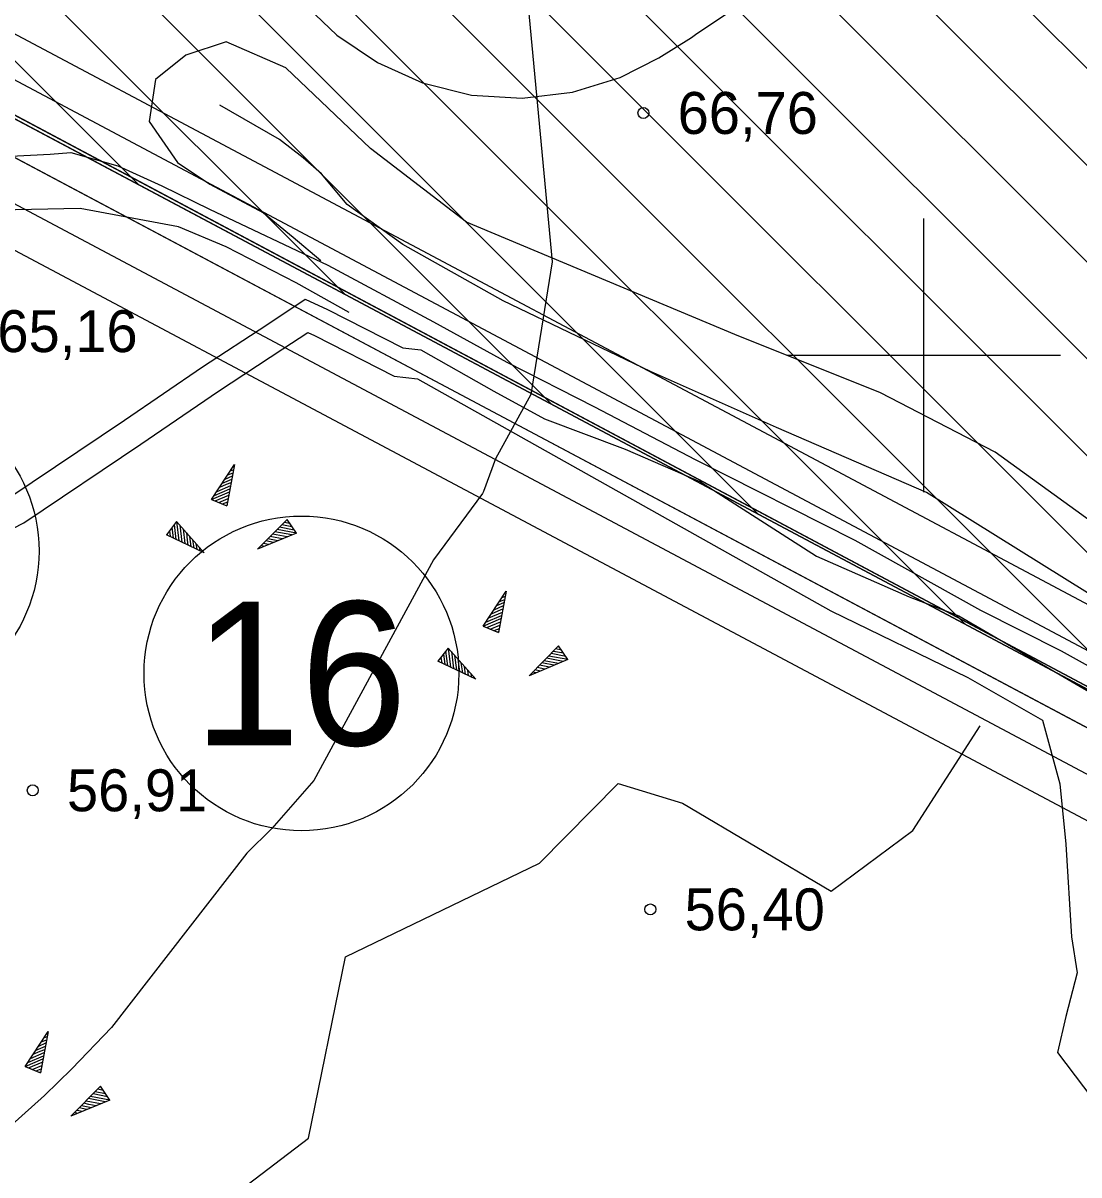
# Model space of a CAD drawing. Extents: x 532503 to 539665, y 6557663 to 6561526.
# Drawn here: x 534947.4 to 535009.1, y 6559752.1 to 6559819.4 of the extents above; entities that cross this region are included whole.
import ezdxf

# ---------------------------------------------------------------- set-up
doc = ezdxf.new("R2010")
doc.units = 0
for name, color, linetype in [('Default', 7, 'Continuous'), ('illumineerimisjooned', 7, 'Continuous'), ('Kaevandatud ala', 7, 'Continuous'), ('kataster', 7, 'Continuous'), ('KORGUS-EH2000', 7, 'Continuous'), ('Lamami horisontaal_EH2000', 7, 'Continuous'), ('ME_aktiivne', 7, 'Continuous'), ('PIIR', 7, 'Continuous'), ('PIIR_me', 7, 'Continuous'), ('Plokid', 7, 'Continuous'), ('RELJEEF', 7, 'Continuous'), ('TM_aktiivne', 7, 'Continuous'), ('VORK', 7, 'Continuous')]:
    doc.layers.add(name, color=color, linetype=linetype)

# ---------------------------------------------------------------- blocks, each defined once
blk = doc.blocks.new('POINT_DISPLAY')
at = {"layer": 'Default'}
blk.add_line((0, 0), (0, 0), dxfattribs=at)

msp = doc.modelspace()

# ---------------------------------------------------------------- linework, layer by layer
at = {"layer": 'illumineerimisjooned'}
for points in [[(534195.15, 6559981.187), (534198.982, 6559981.551), (535160.123, 6560071.768), (535418.528, 6559993.818), (535458.873, 6559929.252), (535494.628, 6559867.696), (535482.599, 6559826.001), (535251.738, 6559649.676), (535250.358, 6559648.526), (535180.445, 6559687.333), (534941.147, 6559814.594), (534876.935, 6559774.719), (534959.617, 6559531.323), (534733.77, 6559483.152), (534375.905, 6559461.866), (534195.514, 6559444.474)], [(535103.273, 6559501.74), (534971.344, 6559496.804), (534876.945, 6559774.719), (534941.147, 6559814.604), (535178.869, 6559688.171)], [(534960.711, 6559535.564), (534879.83, 6559773.686), (534941.24, 6559811.836), (535177.962, 6559685.935)]]:
    msp.add_lwpolyline(points, dxfattribs=at)
msp.add_lwpolyline([(534967.673, 6560049.69), (534974.155, 6559828.082), (535058.693, 6559883.051), (535223.499, 6560002.448), (535218.56, 6560049.918), (535415.933, 6559990.422), (535455.447, 6559927.188), (535490.312, 6559867.164), (535479.121, 6559828.379), (535249.574, 6559653.049), (535182.36, 6559690.845), (534940.993, 6559819.216), (534872.135, 6559776.441), (534954.369, 6559534.338), (534950.911, 6559533.67), (534733.22, 6559487.117), (534375.585, 6559465.864), (534199.951, 6559448.922), (533951.788, 6559660.129), (534200.214, 6559977.649), (534931.627, 6560046.309)], close=True, dxfattribs=at)
at = {"layer": 'Kaevandatud ala'}
for p, q in [((534955.885, 6559847.793), (535038.684, 6559764.994)), ((534952.616, 6559845.405), (535026.601, 6559771.42)), ((534948.592, 6559843.772), (535014.517, 6559777.847)), ((534942.035, 6559839.015), (534990.35, 6559790.7)), ((534947.823, 6559838.884), (535002.434, 6559784.273)), ((534940.755, 6559834.638), (534978.267, 6559797.127)), ((534935.513, 6559834.224), (534966.183, 6559803.553)), ((534932.015, 6559832.065), (534954.1, 6559809.98)), ((534977.01, 6559832.324), (535050.768, 6559758.567)), ((534984.096, 6559830.895), (535062.851, 6559752.14)), ((534996.108, 6559830.198), (535087.018, 6559739.287)), ((534991.44, 6559829.208), (535074.935, 6559745.714))]:
    msp.add_line(p, q, dxfattribs=at)
msp.add_lwpolyline([(534874.54, 6559775.58), (534941.07, 6559816.91), (535181.4, 6559689.09)], dxfattribs=at)
at = {"layer": 'kataster'}
for points in [[(533947.7, 6559658.95), (533949.2, 6559955.8), (534198.28, 6559979.48), (535159.89, 6560069.73), (535417.31, 6559992.13), (535457.22, 6559928.24), (535504.86, 6559846.09), (535250.3, 6559650.84), (535181.52, 6559689.04), (534941.15, 6559817.08), (534874.65, 6559775.26), (534957.01, 6559532.73), (534735.22, 6559485.45), (534375.71, 6559463.85), (534199.28, 6559446.9), (534122.84, 6559439.44), (534110.45, 6559447.36), (534092.53, 6559453.94), (534085.13, 6559454.75)], [(534957.01, 6559532.73), (534874.65, 6559775.26), (534941.15, 6559817.08), (535181.52, 6559689.04), (535104.64, 6559499.79), (534969.93, 6559494.75)]]:
    msp.add_lwpolyline(points, close=True, dxfattribs=at)
at = {"layer": 'KORGUS-EH2000'}
for centre in [(534983.62, 6559814.165), (534947.922, 6559774.569), (534984.024, 6559767.607)]:
    msp.add_circle(centre, 0.32, dxfattribs=at)
at = {"layer": 'Lamami horisontaal_EH2000'}
msp.add_lwpolyline([(534948.61, 6559868.336), (534959.559, 6559855.631), (534962.846, 6559852.329), (534963.478, 6559851.608), (534969.311, 6559840.662), (534970.343, 6559839.3), (534974.316, 6559830.834), (534976.179, 6559827.865), (534978.276, 6559805.462), (534977.047, 6559797.709), (534974.967, 6559793.942), (534974.262, 6559792.029), (534974.206, 6559791.92), (534971.342, 6559788.044), (534964.361, 6559775.147), (534961.905, 6559772.338), (534960.442, 6559770.885), (534952.529, 6559760.708), (534950.203, 6559758.284), (534948.61, 6559756.736), (534944.621, 6559753.17)], dxfattribs=at)
at = {"layer": 'ME_aktiivne'}
msp.add_lwpolyline([(534874.54, 6559775.58), (534941.07, 6559816.91), (535181.4, 6559689.09), (535131.71, 6559566.56), (534957, 6559532.81)], close=True, dxfattribs=at)
at = {"layer": 'PIIR'}
for centre in [(534939.089, 6559788.556), (534963.629, 6559781.403)]:
    msp.add_circle(centre, 9.2, dxfattribs=at)
at = {"layer": 'PIIR_me'}
msp.add_lwpolyline([(534441.63, 6560002.32), (534688.17, 6560025.46), (534931.44, 6560048.3), (534969.61, 6560051.877), (534976.05, 6559831.7), (535057.56, 6559884.7), (535221.39, 6560003.39), (535216.26, 6560052.7), (535417.23, 6559992.12), (535457.16, 6559928.22), (535492.47, 6559867.43), (535480.86, 6559827.19), (535250.12, 6559650.95), (535250.12, 6559650.95), (535181.4, 6559689.09), (534941.07, 6559816.91), (534874.54, 6559775.58), (534957, 6559532.81), (534951.31, 6559531.71), (534733.49, 6559485.13), (534485.11, 6559470.37)], dxfattribs=at)
at = {"layer": 'Plokid'}
for points in [[(535473.831, 6559827.358), (535249.729, 6559656.195), (535183.501, 6559692.956), (534940.9, 6559821.974), (534869.24, 6559777.474), (534950.465, 6559538.369)], [(534963.6, 6559820.725), (534965.689, 6559818.717), (534968.069, 6559817.12), (534970.705, 6559815.928), (534973.573, 6559815.215), (534976.526, 6559815.029), (534979.466, 6559815.379), (534982.252, 6559816.24), (534984.52, 6559817.392), (534986.425, 6559818.585), (534986.744, 6559818.81), (534989.344, 6559820.554)], [(534961.532, 6559540.611), (534882.716, 6559772.654), (534941.333, 6559809.068), (535174.925, 6559684.832)]]:
    msp.add_lwpolyline(points, dxfattribs=at)
at = {"layer": 'RELJEEF'}
for p, q in [((534958.377, 6559791.563), (534959.721, 6559793.611)), ((534959.721, 6559793.611), (534959.273, 6559791.195)), ((534959.641, 6559793.483), (534959.705, 6559793.515)), ((534959.017, 6559792.523), (534959.561, 6559792.763)), ((534959.177, 6559792.763), (534959.593, 6559792.955)), ((534959.321, 6559793.003), (534959.641, 6559793.131)), ((534959.481, 6559793.243), (534959.673, 6559793.323)), ((534958.377, 6559791.563), (534959.417, 6559792.011)), ((534958.537, 6559791.803), (534959.449, 6559792.187)), ((534958.697, 6559792.043), (534959.497, 6559792.379)), ((534958.857, 6559792.283), (534959.257, 6559792.459)), ((534959.257, 6559792.459), (534959.529, 6559792.571)), ((534958.377, 6559791.563), (534959.273, 6559791.195)), ((534958.585, 6559791.483), (534959.385, 6559791.819)), ((534958.793, 6559791.387), (534959.353, 6559791.627)), ((534959.017, 6559791.307), (534959.321, 6559791.435)), ((534959.225, 6559791.227), (534959.273, 6559791.243)), ((534956.324, 6559790.28), (534955.732, 6559789.512)), ((534956.18, 6559790.104), (534956.292, 6559789.24)), ((534956.324, 6559790.28), (534957.94, 6559788.456)), ((534956.324, 6559790.28), (534956.468, 6559789.16)), ((534956.516, 6559790.072), (534956.644, 6559789.08)), ((534961.058, 6559788.664), (534962.786, 6559790.408)), ((534963.074, 6559789.976), (534962.482, 6559790.088)), ((534962.946, 6559790.168), (534962.626, 6559790.232)), ((534962.818, 6559790.36), (534962.754, 6559790.36)), ((534963.33, 6559789.608), (534962.786, 6559790.408)), ((534957.94, 6559788.456), (534955.732, 6559789.512)), ((534955.764, 6559789.56), (534955.78, 6559789.496)), ((534955.908, 6559789.736), (534955.956, 6559789.416)), ((534956.052, 6559789.928), (534956.132, 6559789.336)), ((534956.708, 6559789.848), (534956.82, 6559789)), ((534956.9, 6559789.64), (534956.948, 6559789.192)), ((534957.076, 6559789.416), (534957.172, 6559788.824)), ((534963.33, 6559789.608), (534961.058, 6559788.664)), ((534962.098, 6559789.352), (534961.81, 6559789.416)), ((534962.786, 6559789.384), (534961.938, 6559789.544)), ((534963.058, 6559789.496), (534962.082, 6559789.688)), ((534962.53, 6559789.272), (534962.098, 6559789.352)), ((534963.33, 6559789.608), (534962.21, 6559789.816)), ((534963.202, 6559789.784), (534962.354, 6559789.96)), ((534956.948, 6559789.192), (534956.996, 6559788.904)), ((534957.268, 6559789.208), (534957.332, 6559788.744)), ((534957.46, 6559788.984), (534957.508, 6559788.664)), ((534957.652, 6559788.776), (534957.684, 6559788.568)), ((534961.186, 6559788.712), (534961.138, 6559788.728)), ((534961.458, 6559788.824), (534961.266, 6559788.872)), ((534961.73, 6559788.936), (534961.394, 6559789)), ((534961.986, 6559789.048), (534961.538, 6559789.144)), ((534962.258, 6559789.16), (534961.666, 6559789.272)), ((534957.844, 6559788.552), (534957.86, 6559788.488)), ((534974.253, 6559784.165), (534975.597, 6559786.213)), ((534975.597, 6559786.213), (534975.149, 6559783.797)), ((534975.517, 6559786.085), (534975.581, 6559786.117)), ((534974.893, 6559785.125), (534975.437, 6559785.365)), ((534975.053, 6559785.365), (534975.469, 6559785.557)), ((534975.197, 6559785.605), (534975.517, 6559785.733)), ((534975.357, 6559785.845), (534975.549, 6559785.925)), ((534974.253, 6559784.165), (534975.293, 6559784.613)), ((534974.413, 6559784.405), (534975.325, 6559784.789)), ((534974.573, 6559784.645), (534975.373, 6559784.981)), ((534974.733, 6559784.885), (534975.133, 6559785.061)), ((534975.133, 6559785.061), (534975.405, 6559785.173)), ((534974.253, 6559784.165), (534975.149, 6559783.797)), ((534974.461, 6559784.085), (534975.261, 6559784.421)), ((534974.669, 6559783.989), (534975.229, 6559784.229)), ((534974.893, 6559783.909), (534975.197, 6559784.037)), ((534975.101, 6559783.829), (534975.149, 6559783.845)), ((534972.2, 6559782.883), (534971.608, 6559782.115)), ((534972.056, 6559782.707), (534972.168, 6559781.843)), ((534972.2, 6559782.883), (534973.816, 6559781.059)), ((534972.2, 6559782.883), (534972.344, 6559781.763)), ((534972.392, 6559782.675), (534972.52, 6559781.683)), ((534976.934, 6559781.267), (534978.662, 6559783.011)), ((534978.95, 6559782.579), (534978.358, 6559782.691)), ((534978.822, 6559782.771), (534978.502, 6559782.835)), ((534978.694, 6559782.963), (534978.63, 6559782.963)), ((534979.206, 6559782.211), (534978.662, 6559783.011)), ((534973.816, 6559781.059), (534971.608, 6559782.115)), ((534971.64, 6559782.163), (534971.656, 6559782.099)), ((534971.784, 6559782.339), (534971.832, 6559782.019)), ((534971.928, 6559782.531), (534972.008, 6559781.939)), ((534972.584, 6559782.451), (534972.696, 6559781.603)), ((534972.776, 6559782.243), (534972.824, 6559781.795)), ((534972.952, 6559782.019), (534973.048, 6559781.427)), ((534979.206, 6559782.211), (534976.934, 6559781.267)), ((534977.974, 6559781.955), (534977.686, 6559782.019)), ((534978.662, 6559781.987), (534977.814, 6559782.147)), ((534978.934, 6559782.099), (534977.958, 6559782.291)), ((534978.406, 6559781.875), (534977.974, 6559781.955)), ((534979.206, 6559782.211), (534978.086, 6559782.419)), ((534979.078, 6559782.387), (534978.23, 6559782.563)), ((534972.824, 6559781.795), (534972.872, 6559781.507)), ((534973.144, 6559781.811), (534973.208, 6559781.347)), ((534973.336, 6559781.587), (534973.384, 6559781.267)), ((534973.528, 6559781.379), (534973.56, 6559781.171)), ((534977.062, 6559781.315), (534977.014, 6559781.331)), ((534977.334, 6559781.427), (534977.142, 6559781.475)), ((534977.606, 6559781.539), (534977.27, 6559781.603)), ((534977.862, 6559781.651), (534977.414, 6559781.747)), ((534978.134, 6559781.763), (534977.542, 6559781.875)), ((534973.72, 6559781.155), (534973.736, 6559781.091)), ((534947.474, 6559758.418), (534948.818, 6559760.466)), ((534948.818, 6559760.466), (534948.37, 6559758.05)), ((534948.738, 6559760.338), (534948.802, 6559760.37)), ((534948.274, 6559759.618), (534948.69, 6559759.81)), ((534948.418, 6559759.858), (534948.738, 6559759.986)), ((534948.578, 6559760.098), (534948.77, 6559760.178)), ((534947.634, 6559758.658), (534948.546, 6559759.042)), ((534947.794, 6559758.898), (534948.594, 6559759.234)), ((534947.954, 6559759.138), (534948.354, 6559759.314)), ((534948.114, 6559759.378), (534948.658, 6559759.618)), ((534948.354, 6559759.314), (534948.626, 6559759.426)), ((534947.474, 6559758.418), (534948.514, 6559758.866)), ((534947.474, 6559758.418), (534948.37, 6559758.05)), ((534947.682, 6559758.338), (534948.482, 6559758.674)), ((534947.89, 6559758.242), (534948.45, 6559758.482)), ((534948.114, 6559758.162), (534948.418, 6559758.29)), ((534948.322, 6559758.082), (534948.37, 6559758.098)), ((534950.155, 6559755.52), (534951.883, 6559757.264)), ((534952.043, 6559757.024), (534951.723, 6559757.088)), ((534951.915, 6559757.216), (534951.851, 6559757.216)), ((534952.427, 6559756.464), (534951.883, 6559757.264)), ((534952.427, 6559756.464), (534950.155, 6559755.52)), ((534951.883, 6559756.24), (534951.035, 6559756.4)), ((534952.155, 6559756.352), (534951.179, 6559756.544)), ((534952.427, 6559756.464), (534951.307, 6559756.672)), ((534952.299, 6559756.64), (534951.451, 6559756.816)), ((534952.171, 6559756.832), (534951.579, 6559756.944)), ((534950.555, 6559755.68), (534950.363, 6559755.728)), ((534950.827, 6559755.792), (534950.491, 6559755.856)), ((534951.083, 6559755.904), (534950.635, 6559756)), ((534951.355, 6559756.016), (534950.763, 6559756.128)), ((534951.195, 6559756.208), (534950.907, 6559756.272)), ((534951.627, 6559756.128), (534951.195, 6559756.208)), ((534950.283, 6559755.568), (534950.235, 6559755.584))]:
    msp.add_line(p, q, dxfattribs=at)
for points in [[(535010.727, 6559789.608), (535004.185, 6559794.343), (534997.477, 6559797.806), (534988.968, 6559801.212), (534973.285, 6559807.783), (534967.662, 6559812.098), (534962.717, 6559816.805), (534959.233, 6559818.318), (534956.877, 6559817.549), (534955.098, 6559816.117), (534954.723, 6559813.675), (534956.388, 6559811.264), (534958.274, 6559809.999), (534961.414, 6559808.334), (534963.145, 6559806.903), (534964.755, 6559805.543)], [(535047.455, 6559767.7), (535045.822, 6559765.819), (535042.775, 6559766.983), (535038.612, 6559769.298), (535030.554, 6559774.104), (535021.309, 6559779.446), (535010.921, 6559785.273), (535000.172, 6559791.974), (534991.401, 6559795.786), (534984.042, 6559799.054), (534975.412, 6559803.179), (534969.551, 6559806.479), (534966.309, 6559808.818), (534964.792, 6559810.617), (534963.734, 6559811.535), (534962.353, 6559812.616), (534958.851, 6559814.626)], [(534943.926, 6559811.507), (534948.934, 6559811.75), (534950.157, 6559811.848), (534952.894, 6559811.072), (534955.474, 6559809.906), (534958.257, 6559808.543), (534965.18, 6559805.272), (534971.349, 6559801.964), (534975.639, 6559799.592), (534980.752, 6559796.985), (534986.642, 6559793.917), (534995.987, 6559789.196), (535003.32, 6559785.092), (535008.035, 6559782.716), (535013.956, 6559779.425), (535022.745, 6559775.159), (535031.505, 6559770.264), (535038.015, 6559766.492), (535042.284, 6559764.124), (535044.76, 6559762.654), (535046.987, 6559761.913), (535050.526, 6559759.787), (535053.399, 6559756.557), (535053.749, 6559754.363)], [(534966.413, 6559802.495), (534963.314, 6559804.241), (534959.226, 6559806.349), (534956.45, 6559807.504), (534950.693, 6559808.59), (534945.942, 6559808.482), (534939.275, 6559807.469), (534936.044, 6559806.562), (534932.1, 6559803.022), (534928.693, 6559804.569), (534923.716, 6559801.345), (534920.276, 6559799.267), (534915.665, 6559796.878), (534910.776, 6559794.357), (534905.918, 6559791.333), (534899.817, 6559788.233), (534889.658, 6559782.667), (534885.462, 6559780.463), (534880.206, 6559778.103)], [(534946.533, 6559791.665), (534953.285, 6559796.213), (534957.847, 6559799.322), (534961.608, 6559801.786), (534963.841, 6559803.278), (534965.144, 6559802.684), (534969.55, 6559800.434), (534970.61, 6559800.312)], [(534941.268, 6559787.04), (534947.402, 6559790.204), (534954.241, 6559794.812), (534958.789, 6559797.911), (534962.546, 6559800.372), (534963.997, 6559801.341), (534964.396, 6559801.154), (534969.052, 6559798.781), (534970.415, 6559798.619)], [(534970.61, 6559800.312), (534974.867, 6559797.911), (534977.828, 6559796.283), (534982.547, 6559794.52), (534986.964, 6559792.603), (534993.728, 6559788.262), (534999.15, 6559785.886), (535002.048, 6559784.761), (535015.064, 6559777.195)], [(534970.415, 6559798.619), (534994.566, 6559785.059), (535002.588, 6559781.171), (535006.948, 6559778.677), (535007.966, 6559774.949), (535008.311, 6559771.428), (535008.648, 6559765.994), (535008.973, 6559763.896), (535008.315, 6559761.354), (535007.83, 6559759.242)], [(534945.69, 6559737.942), (534953.976, 6559736.717), (534957.511, 6559740.57), (534959.177, 6559744.854), (534958.555, 6559750.039), (534964.034, 6559754.238), (534966.206, 6559764.827), (534977.543, 6559770.3), (534982.152, 6559774.971), (534985.902, 6559773.808), (534994.598, 6559768.676), (534999.363, 6559772.217), (535003.305, 6559778.331)], [(535007.83, 6559759.242), (535015.903, 6559748.563), (535017.476, 6559737.977), (535018.301, 6559737.855), (535024.429, 6559734.986), (535031.266, 6559731.988), (535038.211, 6559723.99), (535043.824, 6559714.656), (535047.675, 6559707.009), (535061.179, 6559696.438), (535066.266, 6559693.121), (535073.71, 6559686.849), (535077.033, 6559683.833), (535080.737, 6559680.562), (535085.929, 6559676.258), (535091.056, 6559674.474)]]:
    msp.add_lwpolyline(points, dxfattribs=at)
at = {"layer": 'TM_aktiivne'}
for points in [[(535159.92, 6560069.74), (535417.23, 6559992.12), (535457.16, 6559928.22), (535492.47, 6559867.43), (535480.86, 6559827.19), (535250.49, 6559651.24), (535250.13, 6559650.94), (535181.4, 6559689.09), (534941.07, 6559816.9), (534874.53, 6559775.58), (534957, 6559532.81), (534733.5, 6559485.14), (534375.75, 6559463.86), (534199.32, 6559446.85), (534124.95, 6559439.68), (533949.03, 6559659.85), (533949.15, 6559955.79), (534199.17, 6559979.56)], [(534874.54, 6559775.58), (534941.07, 6559816.91), (535181.4, 6559689.09), (535104.64, 6559499.79), (534969.93, 6559494.75)]]:
    msp.add_lwpolyline(points, close=True, dxfattribs=at)
at = {"layer": 'VORK'}
for p, q in [((535000, 6559808.001), (535000, 6559791.999)), ((534991.999, 6559800), (535008.001, 6559800))]:
    msp.add_line(p, q, dxfattribs=at)

# ---------------------------------------------------------------- block references
at = {"layer": 'RELJEEF', "xscale": 160, "yscale": 160}
for p in [(534958.377, 6559791.563), (534956.324, 6559790.28), (534963.33, 6559789.608), (534974.253, 6559784.165), (534972.2, 6559782.883), (534979.206, 6559782.211), (534947.474, 6559758.418), (534952.427, 6559756.464)]:
    msp.add_blockref('POINT_DISPLAY', p, dxfattribs=at)

# ---------------------------------------------------------------- texts
at = {"layer": 'KORGUS-EH2000'}
for s, p in [('66,76 ', (534985.62, 6559812.94)), ('65,16 ', (534945.854, 6559800.186)), ('56,91 ', (534949.922, 6559773.344)), ('56,40 ', (534986.024, 6559766.382))]:
    msp.add_text(s, height=2.45, dxfattribs=at).set_placement(p)
at = {"layer": 'PIIR'}
msp.add_text('16', height=8.4, dxfattribs=at).set_placement((534957.313, 6559777.203))

doc.saveas('drawing.dxf')
